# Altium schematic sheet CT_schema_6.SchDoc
size 278 x 170 mm
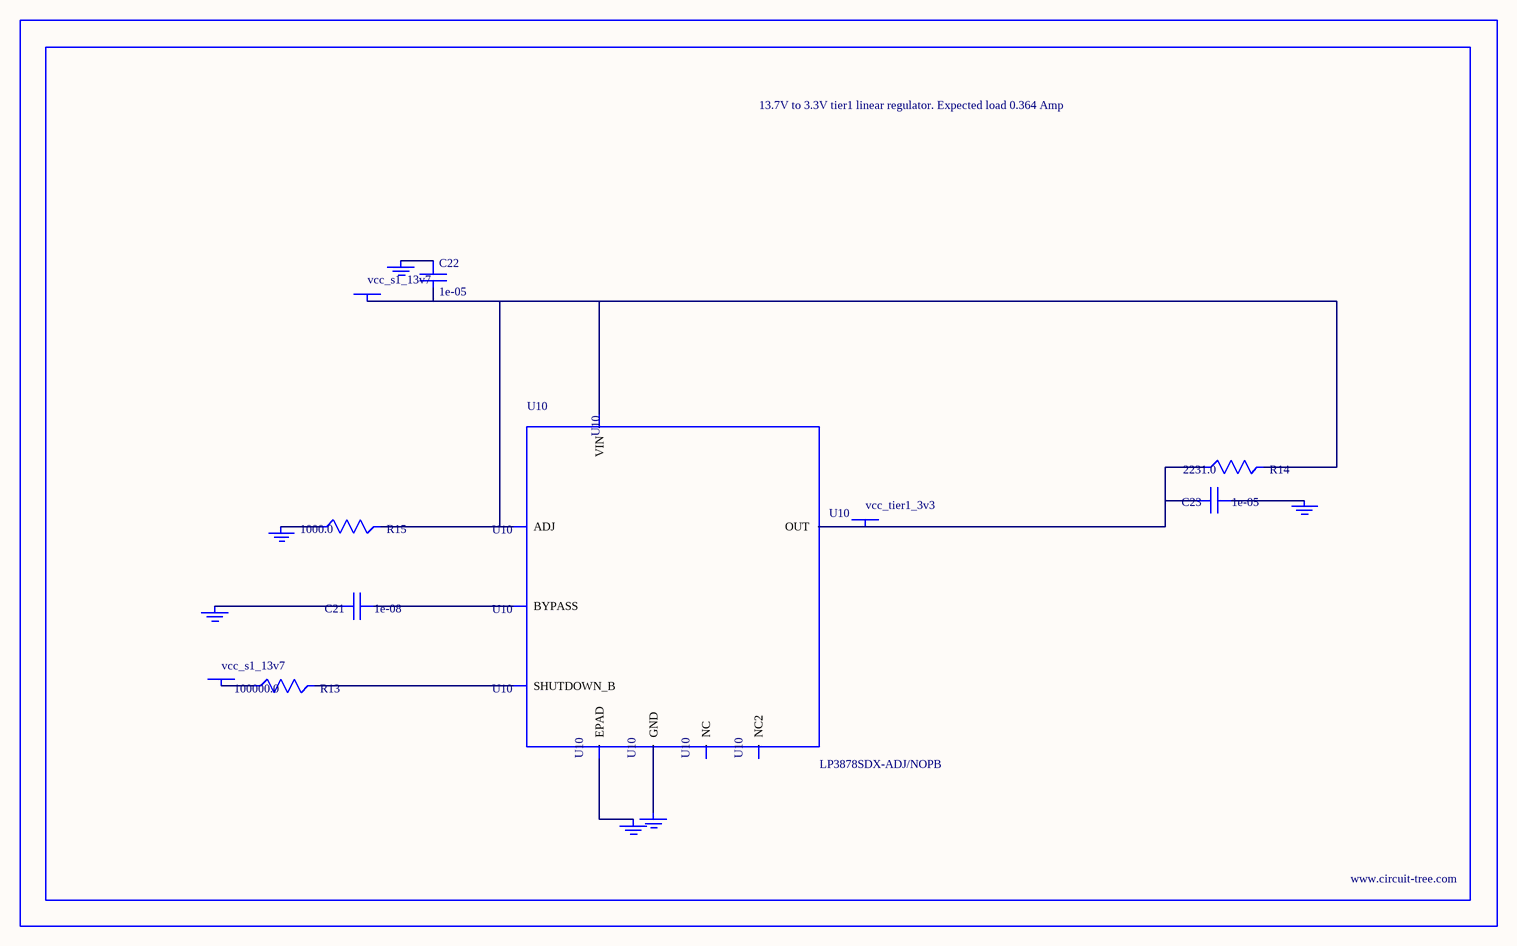
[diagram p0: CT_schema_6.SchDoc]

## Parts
BORDER5  (no value)
C21  1e-08  [C0402]
C22  1e-05  [C1210]
C23  1e-05  [C1210]
GND_INSTANCE_5_0  (no value)
GND_INSTANCE_5_1  (no value)
GND_INSTANCE_5_2  (no value)
GND_INSTANCE_5_3  (no value)
GND_INSTANCE_5_4  (no value)
GND_INSTANCE_5_5  (no value)
POWER_INSTANCE_5_0  vcc_s1_13v7
POWER_INSTANCE_5_1  vcc_s1_13v7
POWER_INSTANCE_5_2  vcc_tier1_3v3
R13  100000.0  [R0603]
R14  2231.0  [R0603]
R15  1000.0  [R0603]
U10  LP3878SDX-ADJ/NOPB  [WSON-8]

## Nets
NetC21_1: C21.1 U10.1(BYPASS)
NetC21_2: C21.2 GND_INSTANCE_5_0.0(GND)
NetC22_1: C22.1 GND_INSTANCE_5_1.0(GND)
NetC22_2: C22.2 POWER_INSTANCE_5_0.0(PWR) R14.2 R15.2 U10.4(VIN) U10.6(ADJ)
NetC23_1: C23.1 GND_INSTANCE_5_2.0(GND)
NetC23_2: C23.2 POWER_INSTANCE_5_2.0(PWR) R14.1 U10.5(OUT)
NetGND_INSTANCE_5_3_0: GND_INSTANCE_5_3.0(GND) R15.1
NetGND_INSTANCE_5_4_0: GND_INSTANCE_5_4.0(GND) U10.PAD(EPAD)
NetGND_INSTANCE_5_5_0: GND_INSTANCE_5_5.0(GND) U10.3(GND)
NetPOWER_INSTANCE_5_1_0: POWER_INSTANCE_5_1.0(PWR) R13.1
NetR13_2: R13.2 U10.8(SHUTDOWN_B)

Not connected (* = marked no-connect by the designer): U10 2(NC) 7(NC2)

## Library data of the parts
BORDER5 = BORDER_PAGE5
C21 = C0402C103K3RAC
C22 = C1210C106K5PACTU
C23 = GRM32DR61E106MA12L
GND_INSTANCE_5_0-GND_INSTANCE_5_5 = GND
POWER_INSTANCE_5_0-POWER_INSTANCE_5_2 = PWR
R13 = RC0603JR-07100KL
R14 = R14
R15 = RC0603JR-071KL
